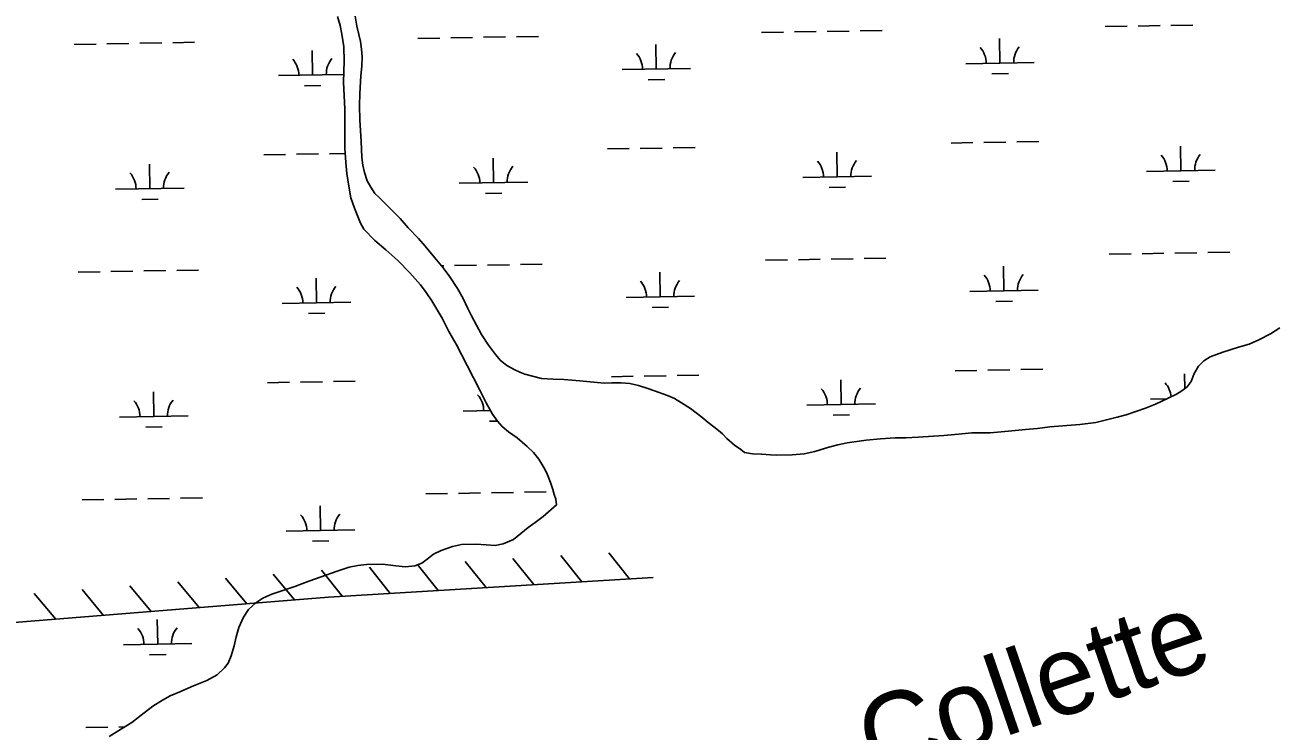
# Model space of a CAD drawing. Extents: x 3892998 to 3931244, y 278583 to 304547.
# Drawn here: x 3913776 to 3915597, y 294629 to 295661 of the extents above; entities that cross this region are included whole.
import ezdxf

# ---------------------------------------------------------------- set-up
doc = ezdxf.new("R2010")
doc.units = 0
for name, color, linetype in [('V-RIVR-IDEN', 7, 'Continuous'), ('V-RRAP-FSHR', 7, 'Continuous'), ('V-TOPO-SHOR', 7, 'Continuous'), ('V-WETL-SWMP', 7, 'Continuous')]:
    doc.layers.add(name, color=color, linetype=linetype)

msp = doc.modelspace()

# ---------------------------------------------------------------- linework, layer by layer
at = {"layer": 'V-RRAP-FSHR'}
for p, q in [((3914519.1, 294843.1), (3914488.7, 294881.3)), ((3914589, 294847.3), (3914558.6, 294885.6)), ((3914658.9, 294851.6), (3914628.5, 294889.8)), ((3914239.6, 294826), (3914209.3, 294864.3)), ((3914309.5, 294830.3), (3914279.1, 294868.5)), ((3914379.4, 294834.6), (3914349, 294872.8)), ((3914449.3, 294838.8), (3914418.9, 294877)), ((3914030.3, 294809.5), (3913999.2, 294847.2)), ((3914100.1, 294815.2), (3914068.9, 294852.8)), ((3914169.8, 294820.8), (3914138.7, 294858.4)), ((3913821, 294792.7), (3913789.8, 294830.3)), ((3913890.7, 294798.3), (3913859.6, 294835.9)), ((3913960.5, 294803.9), (3913929.4, 294841.5))]:
    msp.add_line(p, q, dxfattribs=at)
msp.add_lwpolyline([(3914693.5, 294853.7), (3914219.3, 294824.8), (3913681.4, 294781.4)], dxfattribs=at)
at = {"layer": 'V-TOPO-SHOR'}
for points in [[(3914552.1, 294959.6), (3914551.1, 294968.1), (3914548.8, 294974.7), (3914546.7, 294982.2), (3914543.5, 294992.1), (3914539.3, 295003.4), (3914535, 295011.8), (3914526.6, 295026.3), (3914518.4, 295036.3), (3914509.5, 295045.1), (3914494.6, 295057.6), (3914482, 295066.5), (3914472.8, 295074.2), (3914465.9, 295081.8), (3914458.8, 295092), (3914449.4, 295108.8), (3914440.4, 295127.3), (3914421.7, 295163.3), (3914405.8, 295194.2), (3914395.1, 295212.7), (3914385.1, 295232.1), (3914370.2, 295257.4), (3914361.8, 295269.9), (3914353.8, 295281.1), (3914338.2, 295298.3), (3914320.5, 295316.3), (3914303.2, 295332.1), (3914286.8, 295345.9), (3914271, 295362.2), (3914265.8, 295371.1), (3914262, 295380.8), (3914257.1, 295393.1), (3914252.1, 295407.9), (3914249.1, 295425), (3914246.3, 295443.4), (3914244.8, 295459.6), (3914243, 295480.7), (3914243.1, 295537.5), (3914241.4, 295576.8), (3914242.1, 295607.6), (3914241.5, 295628.7), (3914238.9, 295646.9), (3914236.3, 295659.7), (3914232.6, 295673)], [(3914257.6, 295676.4), (3914260.7, 295658.8), (3914263.5, 295646.8), (3914265.9, 295636.5), (3914267.3, 295625.3), (3914268.3, 295614.1), (3914268.1, 295600.4), (3914266.4, 295586.1), (3914265, 295560.6), (3914264.8, 295543), (3914265.2, 295521.3), (3914266.9, 295490.9), (3914268.2, 295467.2), (3914269.5, 295455.6), (3914271.9, 295445.2), (3914275.9, 295433.1), (3914281.1, 295423.7), (3914287.1, 295414.5), (3914293.4, 295408.4), (3914323.8, 295378), (3914335.5, 295364.2), (3914350.6, 295348.7), (3914360.7, 295337.5), (3914374.6, 295320.5), (3914386.9, 295305.6), (3914396.5, 295292.7), (3914407.6, 295275.7), (3914416.1, 295260.8), (3914422.7, 295246.4), (3914428, 295235.5), (3914442.8, 295208.4), (3914452.9, 295192.8), (3914461.5, 295181.3), (3914470.1, 295170.8), (3914479.7, 295163.2), (3914490.2, 295157.1), (3914498.5, 295153.6), (3914506.1, 295150.4), (3914530.4, 295144.4), (3914547.5, 295143.2), (3914562.7, 295142.7), (3914586.5, 295140.9), (3914621.6, 295137.6), (3914633.1, 295138), (3914646.5, 295137.8), (3914659.5, 295136.8), (3914671.8, 295134), (3914685.5, 295129.5), (3914695.5, 295126.4), (3914714.2, 295119.4), (3914724.3, 295114.9), (3914734.7, 295108.8), (3914747.8, 295100.4), (3914764.4, 295087.8), (3914773.9, 295080), (3914782, 295073.5), (3914788.6, 295068.4), (3914794.7, 295063.3), (3914801, 295056.5), (3914812.1, 295047)], [(3915445.5, 295115.4), (3915457.6, 295121.5), (3915465.5, 295126.2), (3915472.9, 295131.9), (3915478.7, 295139.6), (3915483.4, 295151.3), (3915489.8, 295162.2), (3915497.5, 295170.1), (3915506.5, 295175.7), (3915524.9, 295182.5), (3915548.1, 295189.8), (3915563.4, 295194.5), (3915577.7, 295200.7), (3915594.8, 295209.2), (3915608.6, 295218.2)], [(3914826.6, 295036), (3914838.3, 295034.1), (3914851.6, 295033.5), (3914864.7, 295032.7), (3914873.8, 295032.2), (3914896.3, 295032.5), (3914913.8, 295034), (3914929.6, 295037.6), (3914949.7, 295043.7), (3914963.2, 295047.3), (3914976.8, 295050.1), (3915004.4, 295053.9), (3915025.3, 295055.9), (3915046.7, 295057.3), (3915062.4, 295057.6), (3915080.5, 295058.7), (3915117.8, 295061.1), (3915139.3, 295062.8), (3915158.7, 295064.6), (3915173, 295064.8), (3915185.2, 295065), (3915212.1, 295067.2), (3915237.1, 295069.8), (3915254.5, 295071.4), (3915272.5, 295073.4), (3915316.3, 295076.8), (3915339.7, 295080.1), (3915359.4, 295084.9), (3915370.8, 295087.9), (3915383.8, 295091.3), (3915412.3, 295100.9), (3915426.8, 295106.9), (3915445.5, 295115.4)], [(3914812.1, 295047), (3914821.5, 295040.6), (3914826.6, 295036)], [(3914331.7, 294869.1), (3914345.4, 294870.4), (3914355.8, 294874.7), (3914363.2, 294880.1), (3914372.8, 294887.5), (3914383.8, 294893.1), (3914400.3, 294898.8), (3914413.3, 294901.7), (3914434.3, 294902.2), (3914449.3, 294901.3), (3914462.9, 294900.5), (3914474.5, 294902.5), (3914489.2, 294909.2), (3914511, 294926.6), (3914521.2, 294934), (3914532.8, 294942.7), (3914552.1, 294959.6)], [(3913899, 294621.1), (3913917, 294632.4), (3913932.1, 294642), (3913945.9, 294652.6), (3913962.9, 294665.7), (3913976.9, 294674.4), (3913988.3, 294680.8), (3914002.3, 294686.6), (3914022.1, 294695.2), (3914041.6, 294702.9), (3914056.6, 294711.4), (3914067.4, 294721.6), (3914073, 294728.3), (3914077.3, 294739), (3914081.6, 294753.6), (3914084.5, 294767.1), (3914088.6, 294780.6), (3914095.4, 294795.8), (3914102.6, 294807), (3914113.2, 294816.4), (3914123.4, 294823.6), (3914136.8, 294829.1), (3914170.4, 294840.4), (3914190.6, 294848.3), (3914208.5, 294854.6), (3914230.4, 294862.1), (3914249.3, 294868.8), (3914262.2, 294871.3), (3914274.7, 294872.5), (3914298.3, 294872.9), (3914317.8, 294870.5), (3914331.7, 294869.1)]]:
    msp.add_lwpolyline(points, dxfattribs=at)
at = {"layer": 'V-WETL-SWMP'}
for p, q in [((3914493.7, 295643.3), (3914525.7, 295643.9)), ((3914851.6, 295649.5), (3914883.6, 295650.1)), ((3914899.6, 295650.4), (3914931.6, 295650.9)), ((3914947.6, 295651.2), (3914979.6, 295651.7)), ((3914995.6, 295652), (3915027.6, 295652.6)), ((3915353.4, 295658.2), (3915385.4, 295658.8)), ((3915401.4, 295659), (3915433.4, 295659.6)), ((3915449.4, 295659.9), (3915481.4, 295660.4)), ((3913847.9, 295632.2), (3913879.9, 295632.7)), ((3913895.9, 295633), (3913927.9, 295633.5)), ((3913943.9, 295633.8), (3913975.9, 295634.4)), ((3913991.9, 295634.6), (3914023.9, 295635.2)), ((3914349.8, 295640.8), (3914381.8, 295641.4)), ((3914397.8, 295641.7), (3914429.8, 295642.2)), ((3914445.8, 295642.5), (3914477.7, 295643.1)), ((3914697.9, 295596.1), (3914697.3, 295632.1)), ((3915199.7, 295604.8), (3915199.1, 295640.8)), ((3914196.1, 295587.4), (3914195.5, 295623.4)), ((3914647.9, 295595.3), (3914747.9, 295597)), ((3915149.8, 295603.9), (3915249.7, 295605.7)), ((3915188, 295589.2), (3915212, 295589.6)), ((3914146.1, 295586.6), (3914241.6, 295588.2)), ((3914184.3, 295571.8), (3914208.3, 295572.2)), ((3914686.2, 295580.5), (3914710.2, 295580.9)), ((3914626.5, 295479.4), (3914658.5, 295480)), ((3914674.5, 295480.3), (3914706.5, 295480.8)), ((3914722.5, 295481.1), (3914754.5, 295481.6)), ((3915128.3, 295488.1), (3915160.3, 295488.7)), ((3915176.3, 295489), (3915208.3, 295489.5)), ((3915224.3, 295489.8), (3915256.3, 295490.3)), ((3915463.9, 295447.5), (3915463.3, 295483.5)), ((3914124.7, 295470.7), (3914156.7, 295471.3)), ((3914172.7, 295471.6), (3914204.7, 295472.1)), ((3914220.7, 295472.4), (3914243.6, 295472.8)), ((3914460.3, 295430.1), (3914459.7, 295466.1)), ((3914962.1, 295438.8), (3914961.5, 295474.8)), ((3913958.4, 295421.4), (3913957.8, 295457.4)), ((3915413.9, 295446.6), (3915513.9, 295448.4)), ((3914410.3, 295429.3), (3914510.3, 295431)), ((3914912.1, 295437.9), (3915012.1, 295439.7)), ((3915452.2, 295431.9), (3915476.2, 295432.3)), ((3913908.5, 295420.6), (3914008.4, 295422.3)), ((3914448.5, 295414.5), (3914472.5, 295414.9)), ((3914950.4, 295423.2), (3914974.4, 295423.6)), ((3913946.7, 295405.8), (3913970.7, 295406.2)), ((3914857.4, 295316.9), (3914889.4, 295317.5)), ((3914905.4, 295317.7), (3914937.3, 295318.3)), ((3914953.3, 295318.6), (3914985.3, 295319.1)), ((3915001.3, 295319.4), (3915033.3, 295320)), ((3915359.2, 295325.6), (3915391.2, 295326.1)), ((3915407.2, 295326.4), (3915439.2, 295327)), ((3915455.2, 295327.3), (3915487.2, 295327.8)), ((3915503.2, 295328.1), (3915535.2, 295328.6)), ((3913853.7, 295299.5), (3913885.7, 295300.1)), ((3913901.7, 295300.4), (3913933.7, 295300.9)), ((3913949.7, 295301.2), (3913981.7, 295301.7)), ((3913997.7, 295302), (3914029.7, 295302.6)), ((3914384.3, 295308.7), (3914387.5, 295308.8)), ((3914403.5, 295309), (3914435.5, 295309.6)), ((3914451.5, 295309.9), (3914483.5, 295310.4)), ((3914499.5, 295310.7), (3914531.5, 295311.3)), ((3914703.7, 295263.5), (3914703, 295299.5)), ((3915205.5, 295272.2), (3915204.9, 295308.2)), ((3914201.8, 295254.8), (3914201.2, 295290.8)), ((3914653.7, 295262.6), (3914753.7, 295264.4)), ((3915155.5, 295271.3), (3915255.5, 295273)), ((3914151.8, 295253.9), (3914251.8, 295255.7)), ((3914691.9, 295247.9), (3914715.9, 295248.3)), ((3915193.8, 295256.5), (3915217.8, 295257)), ((3914190.1, 295239.2), (3914214.1, 295239.6)), ((3915134.1, 295155.5), (3915166.1, 295156)), ((3915182.1, 295156.3), (3915214.1, 295156.9)), ((3915230.1, 295157.2), (3915262.1, 295157.7)), ((3914130.4, 295138.1), (3914162.4, 295138.7)), ((3914178.4, 295139), (3914210.4, 295139.5)), ((3914226.4, 295139.8), (3914258.4, 295140.3)), ((3914632.3, 295146.8), (3914664.3, 295147.4)), ((3914680.3, 295147.6), (3914712.3, 295148.2)), ((3914728.3, 295148.5), (3914760.2, 295149)), ((3914967.9, 295106.2), (3914967.2, 295142.2)), ((3915469.5, 295129.2), (3915469.1, 295150.9)), ((3913964.2, 295088.8), (3913963.6, 295124.8)), ((3914917.9, 295105.3), (3915017.9, 295107)), ((3915419.7, 295114), (3915443.3, 295114.4)), ((3913914.2, 295087.9), (3914014.2, 295089.7)), ((3914416, 295096.6), (3914455.8, 295097.3)), ((3914454.3, 295081.9), (3914465.7, 295082.1)), ((3914956.1, 295090.5), (3914980.1, 295091)), ((3913952.5, 295073.2), (3913976.5, 295073.6)), ((3914361.3, 294975.6), (3914393.3, 294976.1)), ((3914409.3, 294976.4), (3914441.3, 294977)), ((3914457.3, 294977.3), (3914489.3, 294977.8)), ((3914505.3, 294978.1), (3914537.3, 294978.6)), ((3913859.5, 294966.9), (3913891.4, 294967.5)), ((3913907.4, 294967.7), (3913939.4, 294968.3)), ((3913955.4, 294968.6), (3913987.4, 294969.1)), ((3914003.4, 294969.4), (3914035.4, 294970)), ((3914207.6, 294922.2), (3914207, 294958.2)), ((3914157.6, 294921.3), (3914257.6, 294923)), ((3914195.9, 294906.5), (3914219.9, 294907)), ((3913970, 294756.2), (3913969.3, 294792.2)), ((3913920, 294755.3), (3914020, 294757)), ((3913958.2, 294740.5), (3913982.2, 294741)), ((3913865.2, 294634.3), (3913897.2, 294634.8)), ((3913913.2, 294635.1), (3913921.5, 294635.3))]:
    msp.add_line(p, q, dxfattribs=at)
for points in [[(3914232.6, 295673), (3914236.3, 295659.7), (3914238.9, 295646.9), (3914241.5, 295628.7)], [(3914374.6, 295320.5), (3914360.7, 295337.5), (3914350.6, 295348.7), (3914335.5, 295364.2), (3914323.8, 295378), (3914293.4, 295408.4), (3914287.1, 295414.5), (3914281.1, 295423.7), (3914275.9, 295433.1), (3914271.9, 295445.2), (3914269.5, 295455.6), (3914268.2, 295467.2), (3914266.9, 295490.9), (3914265.2, 295521.3), (3914264.8, 295543), (3914265, 295560.6), (3914266.4, 295586.1), (3914268.1, 295600.4), (3914268.3, 295614.1), (3914267.3, 295625.3), (3914265.9, 295636.5), (3914263.5, 295646.8), (3914260.7, 295658.8), (3914257.6, 295676.4)], [(3914241.5, 295628.7), (3914242.1, 295607.6), (3914241.4, 295576.8), (3914243.1, 295537.5), (3914243, 295480.7), (3914244.8, 295459.6), (3914246.3, 295443.4), (3914249.1, 295425), (3914252.1, 295407.9), (3914257.1, 295393.1), (3914262, 295380.8), (3914265.8, 295371.1), (3914271, 295362.2), (3914286.8, 295345.9), (3914303.2, 295332.1), (3914320.5, 295316.3), (3914338.2, 295298.3), (3914353.8, 295281.1), (3914361.8, 295269.9), (3914370.2, 295257.4), (3914385.1, 295232.1), (3914395.1, 295212.7), (3914405.8, 295194.2), (3914421.7, 295163.3), (3914440.4, 295127.3), (3914449.4, 295108.8), (3914458.8, 295092), (3914465.9, 295081.8), (3914472.8, 295074.2), (3914482, 295066.5), (3914494.6, 295057.6), (3914509.5, 295045.1), (3914518.4, 295036.3), (3914526.6, 295026.3), (3914535, 295011.8), (3914539.3, 295003.4), (3914543.5, 294992.1), (3914546.7, 294982.2), (3914548.8, 294974.7), (3914551.1, 294968.1), (3914552.1, 294959.6), (3914532.8, 294942.7), (3914521.2, 294934), (3914511, 294926.6), (3914489.2, 294909.2), (3914474.5, 294902.5), (3914462.9, 294900.5), (3914449.3, 294901.3), (3914434.3, 294902.2), (3914413.3, 294901.7), (3914400.3, 294898.8), (3914383.8, 294893.1), (3914372.8, 294887.5), (3914363.2, 294880.1), (3914355.8, 294874.7), (3914345.4, 294870.4), (3914331.7, 294869.1), (3914317.8, 294870.5), (3914298.3, 294872.9), (3914274.7, 294872.5), (3914262.2, 294871.3), (3914249.3, 294868.8), (3914230.4, 294862.1), (3914208.5, 294854.6), (3914190.6, 294848.3), (3914170.4, 294840.4), (3914136.8, 294829.1), (3914123.4, 294823.6), (3914113.2, 294816.4), (3914102.6, 294807), (3914095.4, 294795.8), (3914088.6, 294780.6), (3914084.5, 294767.1), (3914081.6, 294753.6), (3914077.3, 294739), (3914073, 294728.3), (3914067.4, 294721.6), (3914056.6, 294711.4), (3914041.6, 294702.9), (3914022.1, 294695.2), (3914002.3, 294686.6), (3913988.3, 294680.8), (3913976.9, 294674.4), (3913962.9, 294665.7), (3913945.9, 294652.6), (3913932.1, 294642), (3913917, 294632.4), (3913899, 294621.1)], [(3915608.6, 295218.2), (3915594.8, 295209.2), (3915577.7, 295200.7), (3915563.4, 295194.5), (3915548.1, 295189.8), (3915524.9, 295182.5), (3915506.5, 295175.7), (3915497.5, 295170.1), (3915489.8, 295162.2), (3915483.4, 295151.3), (3915478.7, 295139.6), (3915472.9, 295131.9), (3915465.5, 295126.2), (3915457.6, 295121.5), (3915445.5, 295115.4), (3915426.8, 295106.9), (3915412.3, 295100.9), (3915383.8, 295091.3), (3915370.8, 295087.9), (3915359.4, 295084.9), (3915339.7, 295080.1), (3915316.3, 295076.8), (3915272.5, 295073.4), (3915254.5, 295071.4), (3915237.1, 295069.8), (3915212.1, 295067.2), (3915185.2, 295065), (3915173, 295064.8), (3915158.7, 295064.6), (3915139.3, 295062.8), (3915117.8, 295061.1), (3915080.5, 295058.7), (3915062.4, 295057.6), (3915046.7, 295057.3), (3915025.3, 295055.9), (3915004.4, 295053.9), (3914976.8, 295050.1), (3914963.2, 295047.3), (3914949.7, 295043.7), (3914929.6, 295037.6), (3914913.8, 295034), (3914896.3, 295032.5), (3914873.8, 295032.2), (3914864.7, 295032.7), (3914851.6, 295033.5), (3914838.3, 295034.1), (3914826.6, 295036), (3914821.5, 295040.6), (3914812.1, 295047), (3914801, 295056.5), (3914794.7, 295063.3), (3914788.6, 295068.4), (3914782, 295073.5), (3914773.9, 295080), (3914764.4, 295087.8), (3914747.8, 295100.4), (3914734.7, 295108.8), (3914724.3, 295114.9), (3914714.2, 295119.4), (3914695.5, 295126.4), (3914685.5, 295129.5), (3914671.8, 295134), (3914659.5, 295136.8), (3914646.5, 295137.8), (3914633.1, 295138), (3914621.6, 295137.6), (3914586.5, 295140.9), (3914562.7, 295142.7), (3914547.5, 295143.2), (3914530.4, 295144.4), (3914506.1, 295150.4), (3914498.5, 295153.6), (3914490.2, 295157.1), (3914479.7, 295163.2), (3914470.1, 295170.8), (3914461.5, 295181.3), (3914452.9, 295192.9), (3914442.8, 295208.4), (3914428, 295235.5), (3914422.7, 295246.4), (3914416.1, 295260.8), (3914407.6, 295275.7), (3914396.5, 295292.7), (3914386.9, 295305.6), (3914374.6, 295320.5)]]:
    msp.add_lwpolyline(points, dxfattribs=at)
for centre, start, end in [((3915144.5, 295604.3), 0.2199, 41.7635), ((3915255, 295606.2), 140.2199, 181.7635), ((3914140.8, 295587), 0.2199, 41.7635), ((3914251.3, 295588.9), 140.2199, 181.7635), ((3914642.7, 295595.6), 0.2199, 41.7635), ((3914753.1, 295597.6), 140.2199, 181.7635), ((3914906.9, 295438.3), 0.2199, 41.7635), ((3915017.3, 295440.2), 140.2199, 181.7635), ((3915408.7, 295447), 0.2199, 41.7635), ((3915519.2, 295448.9), 140.2199, 181.7635), ((3913903.2, 295421), 0.2199, 41.7635), ((3914013.7, 295422.9), 140.2199, 181.7635), ((3914405, 295429.6), 0.2199, 41.7635), ((3914515.5, 295431.6), 140.2199, 181.7635), ((3914648.4, 295263), 0.2199, 41.7635), ((3914758.9, 295264.9), 140.2199, 181.7635), ((3915150.3, 295271.7), 0.2199, 41.7635), ((3915260.7, 295273.6), 140.2199, 181.7635), ((3914146.6, 295254.3), 0.2199, 41.7635), ((3914257.1, 295256.2), 140.2199, 181.7635), ((3915414.5, 295114.4), 5.0012, 41.7635), ((3914410.8, 295097), 0.2199, 41.7635), ((3914912.6, 295105.7), 0.2199, 41.7635), ((3915023.1, 295107.6), 140.2199, 181.7635), ((3913909, 295088.3), 0.2199, 41.7635), ((3914019.4, 295090.2), 140.2199, 181.7635), ((3914152.4, 294921.7), 0.2199, 41.7635), ((3914262.8, 294923.6), 140.2199, 181.7635), ((3913914.7, 294755.7), 0.2199, 41.7635), ((3914025.2, 294757.6), 140.2199, 181.7635)]:
    msp.add_arc(centre, 35.2, start, end, dxfattribs=at)

# ---------------------------------------------------------------- texts
at = {"layer": 'V-RIVR-IDEN'}
msp.add_text('Collette', height=116, rotation=18.973, dxfattribs=at).set_placement((3915017.8, 294555.8))

doc.saveas('drawing.dxf')
